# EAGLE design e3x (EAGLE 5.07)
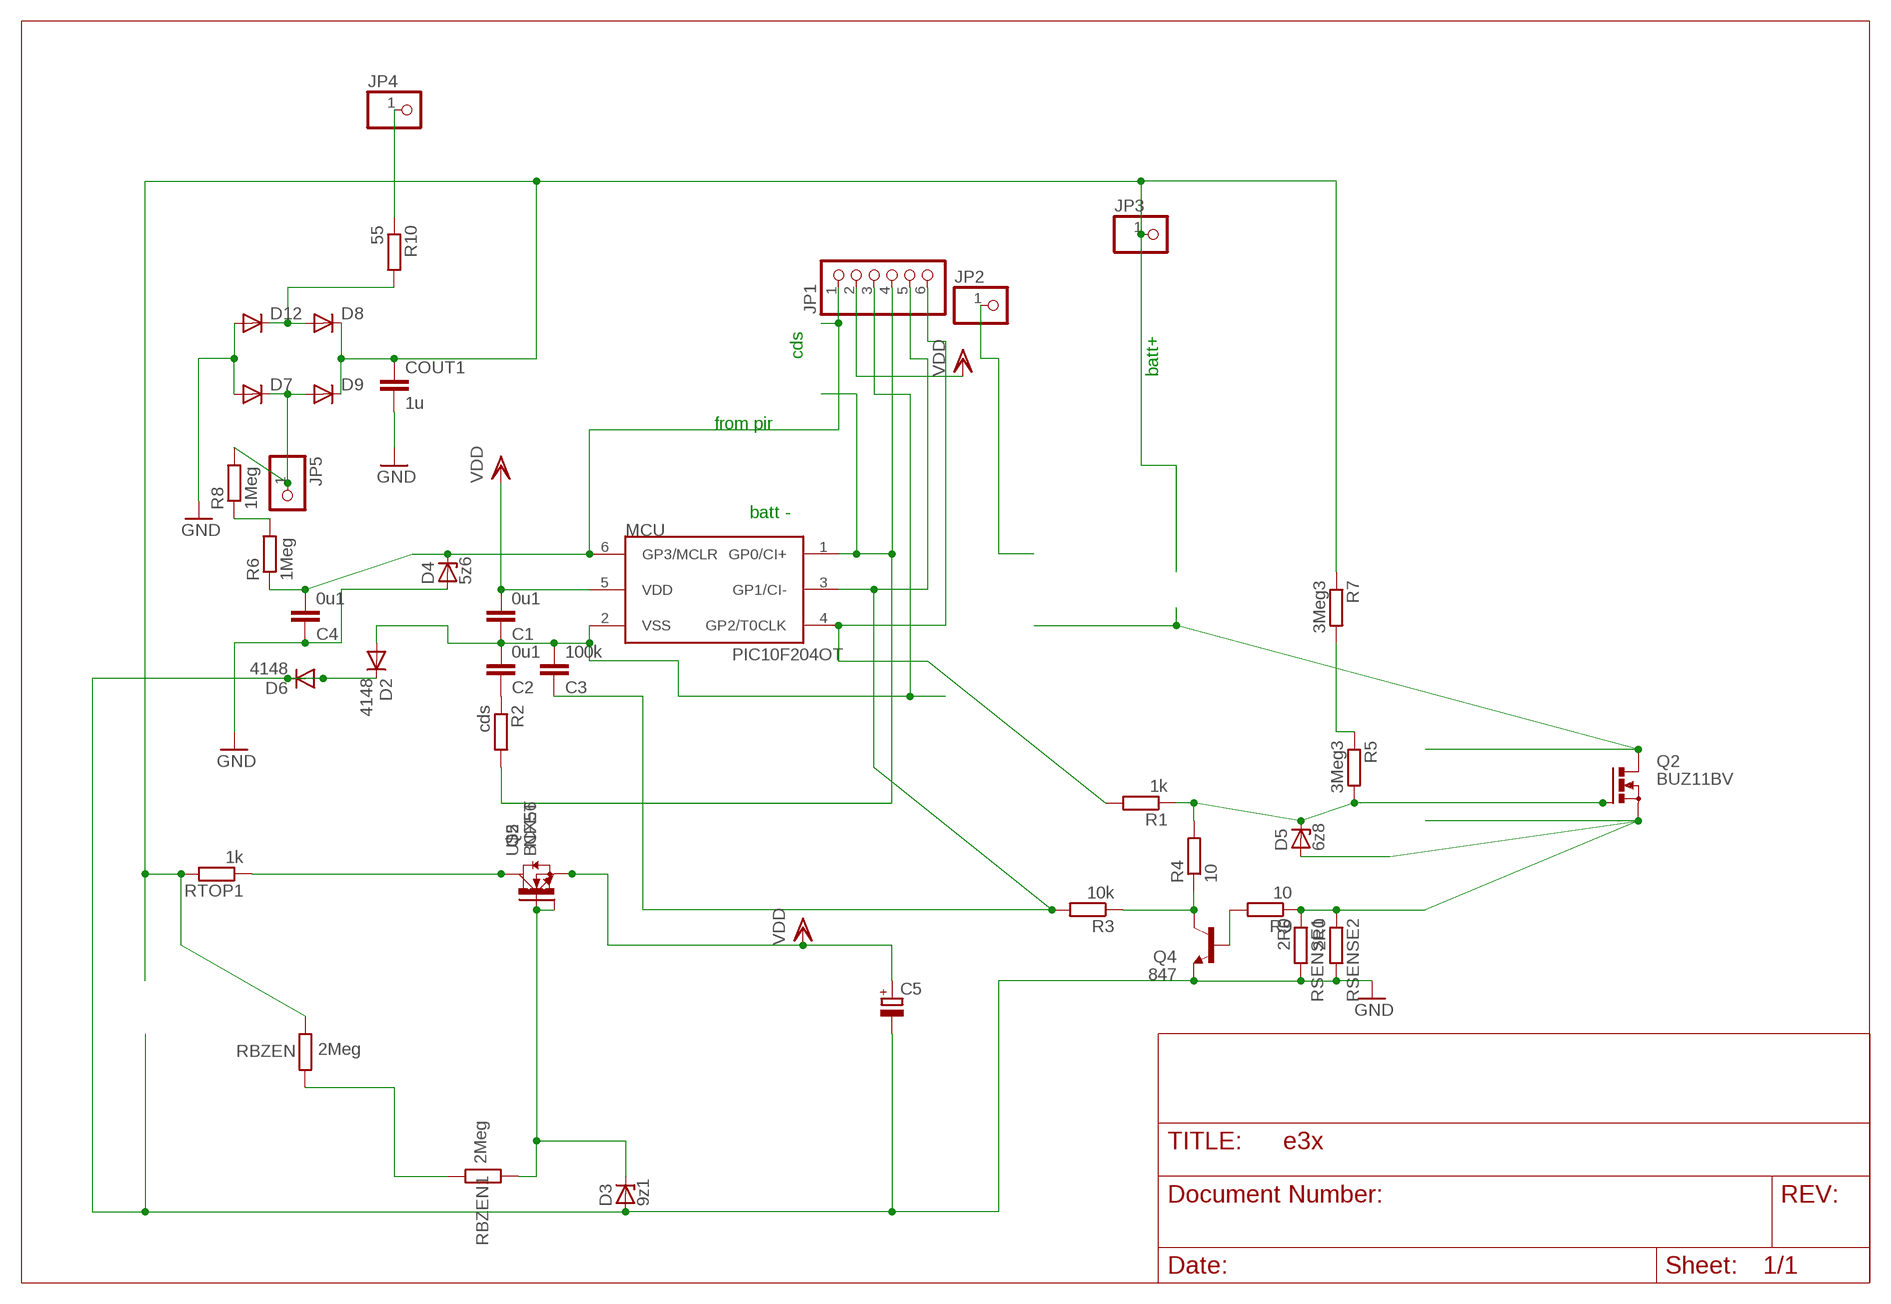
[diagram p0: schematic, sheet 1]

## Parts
C1  0u1  C-EUC0805  [C0805]
C2  0u1  C-EUC0805  [C0805]
C3  100k  C-EUC0805  [C0805]
C4  0u1  C-EUC1206  [C1206]
C5  CPOL-EUSANYO_SMD_C6  [SANYO-OSCON_SMD_C6]
COUT1  1u  C-EU075-032X103  [C075-032X103]
D2  4148  1N4148MINIMELF  [MINIMELF]
D3  9z1  ZENER-DIODESOD80C  [SOD80C]
D4  5z6  ZENER-DIODESOD80C  [SOD80C]
D5  6z8  ZENER-DIODESOD80C  [SOD80C]
D6  4148  1N4148MINIMELF  [MINIMELF]
D7  DIODE-SMA-DO214  [SMA-DO214AC]
D8  DIODE-SMA-DO214  [SMA-DO214AC]
D9  DIODE-SMA-DO214  [SMA-DO214AC]
D12  DIODE-SMA-DO214  [SMA-DO214AC]
JP1  PINHD-1X6  [1X06BOX]
JP2  PINHD-1X11MM6  [1X1MM8]
JP3  PINHD-1X11MM6  [1X1MM8]
JP4  PINHD-1X11MM6  [1X1MM8]
JP5  PINHD-1X11MM6  [1X1MM8]
MCU  PIC10F204OT  [SOT23-6]
Q2  BUZ11BV  [TO220BV]
Q4  847  BC847ASMD  [SOT23]
Q5  NFET  N-HEXFET_DPAK-  [TO252]
R1  1k  R-EU_R0805  [R0805]
R2  cds  R-EU_0204/2V  [0204V]
R3  10k  R-EU_R0805  [R0805]
R4  10  R-EU_R1206  [R1206]
R5  3Meg3  R-EU_R1206  [R1206]
R6  1Meg  R-EU_R1206  [R1206]
R7  3Meg3  R-EU_R1206  [R1206]
R8  1Meg  R-EU_R1206  [R1206]
R9  10  R-EU_R0805  [R0805]
R10  55  R-EU_0207/35  [0207/35]
RBZEN  2Meg  R-EU_R1206  [R1206]
RBZEN1  2Meg  R-EU_R1206  [R1206]
RSENSE1  2R0  R-EU_R1210  [R1210]
RSENSE2  2R0  R-EU_R2512  [R2512]
RTOP1  1k  R-EU_R1206  [R1206]
U$2  BCX56  [SOT223]

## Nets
AC1: JP4.1 R10.1
AC2: D7.K(C) D9.A JP5.1 R8.2
ACR: D8.A D12.K(C) R10.2
C: Q5.3(D) RTOP1.1 U$2.2(C)
CB: D3.C Q5.1(G) RBZEN1.2 U$2.1(B)
GND: C4.1 C5.- COUT1.2 D2.C D3.A D4.A D6.A D6.C D7.A D12.A Q4.2(E) RSENSE1.2 RSENSE2.2
HOT: Q2.D
LED-: JP2.1
N$1: Q4.3(C) R3.1 R4.1
N$2: JP1.4 MCU.1(GP0/CI+) R2.2
N$3: C4.2 D4.C JP1.1 MCU.6(GP3/MCLR) R6.1
N$4: R5.1 R7.2
N$5: C3.1 JP1.5 MCU.3(GP1/CI-) R3.2
N$6: RBZEN1.1 RBZEN.2
N$7: D5.C Q2.G R1.1 R4.2 R5.2
N$8: C2.1 R2.1
N$9: R6.2 R8.1
N$10: Q4.1(B) R9.2
N$14: JP1.6 MCU.4(GP2/T0CLK) R1.2
N$17: D5.A Q2.S R9.1 RSENSE1.1 RSENSE2.1
VDD: C1.2 C5.+ JP1.2 MCU.5(VDD) Q5.2(S) U$2.3(E)
VPLUS: COUT1.1 D8.K(C) D9.K(C) JP3.1 R7.1 RBZEN.1 RTOP1.2
VSS: C1.1 C2.2 C3.2 D2.A JP1.3 MCU.2(VSS)

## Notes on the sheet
- cds
- batt+
- from pir
- batt -

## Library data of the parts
C1-C4 COUT1 = rcl:C-EU: CAPACITOR, European symbol
C5 = rcl-2:CPOL-EU: POLARIZED CAPACITOR, European symbol
D2 D6 = diode-1:1N4148: DIODE
D3-D5 = diode:ZENER-DIODE: Z-Diode
D7-D9 D12 = diode:DIODE-: DIODE
JP1 = pinhead:PINHD-1X6: PIN HEADER
JP2-JP5 = pinhead:PINHD-1X1: PIN HEADER
MCU = microchip-3:PIC10F2*: uPC nW 0,25/0,5k Program Flash memory Comparator
Q2 = transistor-power:BUZ11: N-CHANNEL MOS FET
Q4 = transistor-npn:BC847*: NPN Transistor
Q5 = transistor-power:N-HEXFET_?-*: HEXFET® Power MOSFET
R1-R5 R7 R9 RBZEN RBZEN1 RSENSE1 RSENSE2 RTOP1 = rcl:R-EU_: RESISTOR, European symbol
R6 R8 R10 = rcl-2:R-EU_: RESISTOR, European symbol
U$2 = transistor-power:BCX56

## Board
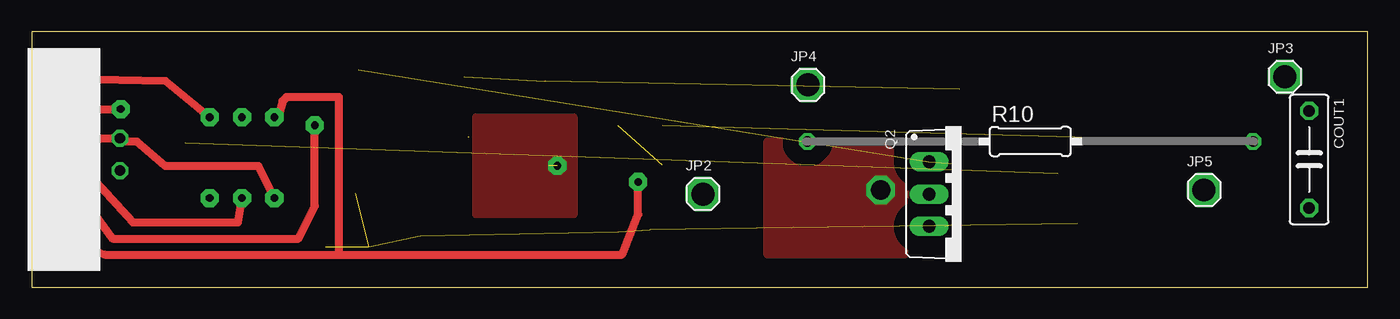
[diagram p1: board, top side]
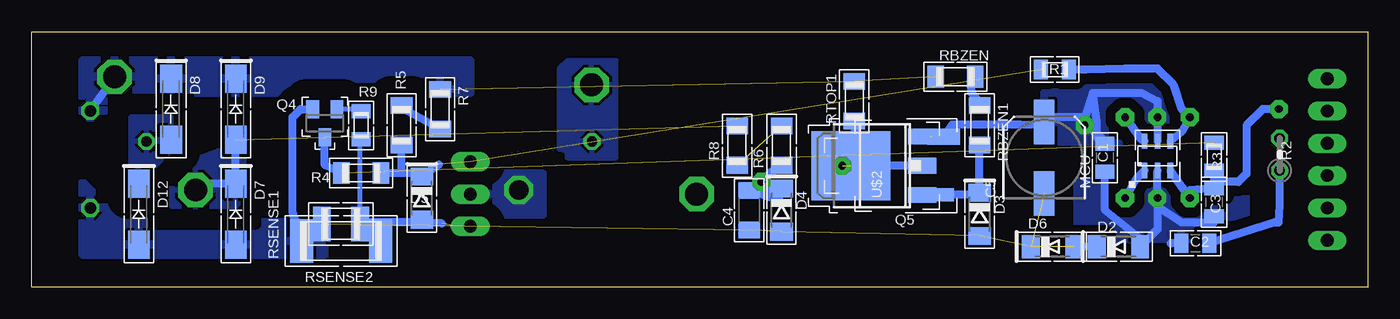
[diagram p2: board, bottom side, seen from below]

Size 104.93 x 20.04 mm. Coordinates in mm from the lower left corner, seen from the top.
Outline: 0,0 104.93,0 104.93,20.04 0,20.04 0,0
Copper layers (1*16): Top 0.035mm / dielectric 1.5mm / Bottom 0.035mm
Design rules "default *": minimum track width 10mil, minimum drill 24mil, track to track 8mil, track to pad 8mil, pad to pad 8mil, via to via 8mil, smd to smd 8mil, copper to edge 20mil, drill to drill 8mil, minimum pad ring 10mil, minimum via ring 8mil, stop-mask expansion 4mil, vias tented up to drill 0mil, thermal gap 10mil

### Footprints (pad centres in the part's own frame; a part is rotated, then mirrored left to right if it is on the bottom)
C0805 = smd 1.1 x 1.5: 1 -1.1,0; 2 1.1,0
C1206 = smd 1.3 x 1.7: 1 -1.55,0; 2 1.55,0
SANYO-OSCON_SMD_C6 = smd 3.5 x 1.6: + 2.8,0; - -2.8,0
C075-032X103 = drill 0.914 octagon: 1 -3.81,0; 2 3.81,0
MINIMELF = smd 1.4 x 1.8: A 1.7,0; C -1.7,0
SOD80C = smd 1.4 x 1.8: A 1.7,0; C -1.7,0
SMA-DO214AC = smd 2.2 x 1.7: A 2.4,0; K -2.4,0
1X06BOX = drill 1 long: 1 -6.35,0; 2 -3.81,0; 3 -1.27,0; 4 1.27,0; 5 3.81,0 | drill 1.016 long: 6 6.35,0
1X1MM8 = drill 1.8 pad 2.54 octagon: 1 0,0
SOT23-6 = smd 0.45 x 1.2: 1 -1.016,-1.15; 2 0,-1.15; 3 1.016,-1.15; 4 1.016,1.15; 5 0,1.15; 6 -1.016,1.15
TO220BV = drill 1.016 long: D 0,-2.54; G -2.54,-2.54; S 2.54,-2.54
SOT23 = smd 1 x 1.4: 1 -0.95,-1.1; 2 0.95,-1.1; 3 0,1.1
TO252 = smd 1 x 1.6: 1 -2.28,-3.53 | smd 1.27 x 2.54: 2 2.28,-3.53 | smd 5.4 x 6.2: 3 0,3.77
R0805 = smd 1.1 x 1.5: 1 -1.1,0; 2 1.1,0
0204V = drill 0.813 octagon: 1 -1.27,0; 2 1.27,0
R1206 = smd 1.3 x 1.7: 1 -1.55,0; 2 1.55,0
0207/35 = drill 0.813 octagon: 1 -17.5,0; 2 17.5,0
R1210 = smd 1.4 x 2.7: 1 -1.5,0; 2 1.5,0
R2512 = smd 1.8 x 3.4: 1 -3.1,0; 2 3.1,0
SOT223 = smd 1.219 x 2.235: 1 -2.311,-3.099; 2 0,-3.099; 3 2.311,-3.099 | smd 3.6 x 2.2: 4 0,3.099

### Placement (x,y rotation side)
C1  20.64,10.16 90 bottom
C2  13.53,3.43 180 bottom
C3  12.06,6.67 270 bottom
C4  48.58,6.03 90 bottom
C5  25.4,10.16 90 bottom
COUT1  100.33,10.02 270 top
D2  19.57,3.17 0 bottom
D3  30.48,5.71 270 bottom
D4  46.04,6.03 270 bottom
D5  74.3,6.98 270 bottom
D6  24.77,3.17 0 bottom
D7  88.9,5.71 270 bottom
D8  93.98,13.97 270 bottom
D9  88.9,13.97 270 bottom
D12  96.52,5.71 270 bottom
JP1  3.17,10.02 90 top
JP2  52.7,7.3 0 top
JP3  98.42,16.51 0 top
JP4  60.96,15.88 0 top
JP5  92.08,7.62 0 top
MCU  16.51,10.3 0 bottom
Q2  73.03,7.3 270 top
Q4  81.92,12.87 180 bottom
Q5  36.83,9.53 90 bottom
R1  24.57,17.08 0 bottom
R2  6.92,10.41 90 bottom
R3  12.06,10.22 270 bottom
R4  79.06,8.95 0 bottom
R5  75.88,12.7 270 bottom
R6  46.04,11.11 90 bottom
R7  72.86,13.97 270 bottom
R8  49.53,11.11 90 bottom
R9  79.06,12.7 90 bottom
R10  78.42,11.43 0 top
RBZEN  32.38,16.51 0 bottom
RBZEN1  30.48,12.7 270 bottom
RSENSE1  80.64,4.95 180 bottom
RSENSE2  80.64,3.62 180 bottom
RTOP1  40.32,14.61 90 bottom
U$2  38.1,9.53 90 bottom

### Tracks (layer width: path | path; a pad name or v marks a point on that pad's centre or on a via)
AC1
  pour Bottom (isolate 1.422, rank 2): 59.05,17.78 62.87,17.78 63.5,17.14 63.5,10.79 62.87,10.16 59.05,10.16
AC2  (1 unrouted)
  Bottom 0.61: D9.A D7.K 92.08,8.12 JP5.1
  pour Bottom (isolate 1.422, rank 2): 88.27,11.43 93.34,9.53 93.98,8.89 93.98,6.35 88.9,6.35 88.27,6.98
ACR
  Bottom 0.61: D8.A 93.98,11.43
  pour Bottom (isolate 1.422): 93.98,13.33 97.16,13.33 97.16,12.06 97.16,8.89 95.89,8.89 93.98,10.79 93.98,12.06
C  (via drill 0.6 pad 1.42)  (1 unrouted)
  Bottom 0.61: 40.01,9.53 40.51,10.54 | 40.51,10.54 40.64,10.79 40.64,11.43 41.27,11.43 | U$2.2 39.37,9.53 | 39.37,9.53 40.01,9.53 | 39.37,9.53 41.91,10.79 | 40.01,9.53 Q5.3 | RTOP1.1 40.17,10.88 40.51,10.54
  other vias: 41.27,9.53
  pour Top (isolate 0.61, rank 4): 34.92,13.33 42.55,13.33 42.55,5.71 34.92,5.71
CB
  Bottom 0.61: RBZEN1.2 D3.C 30.65,7.24 Q5.1 33.33,7.21 U$2.1
GND  (6 unrouted)
  Bottom 0.61: D2.C D6.A | RSENSE1.2 83.48,4.84 RSENSE2.2 84.45,5.89 84.45,13.33 83.82,13.97 Q4.2
  pour Bottom (isolate 1.676, rank 4): 81.92,2.54 81.92,3.17 83.82,5.08 97.79,5.08 100.97,8.26 100.97,2.54
HOT  (via drill 1.5 pad 1.42)
  other vias: 66.67,7.62
  pour Bottom (isolate 1.27): 64.77,8.89 71.12,8.89 71.12,5.71 64.77,5.71
  pour Top (isolate 1.27): 57.78,11.43 66.67,11.43 68.58,9.53 68.58,2.54 57.78,2.54
N$1  (1 unrouted)
  Bottom 0.61: Q4.3 81.92,9.57 R4.1
N$2  (via drill 0.6 pad 1.42)
  Top 0.61: v19.05,6.98 17.78,9.53 10.48,9.53 8.26,11.43 7.18,11.43 R2.2 5.33,11.68 5.08,11.43 3.31,11.43 JP1.4
  Bottom 0.61: MCU.1 18.16,8.51 v19.05,6.98
N$3  (via drill 0.6 pad 1.42)
  Top 0.61: JP1.1 5.71,2.54 24.13,2.54 | 24.13,2.54 24.13,14.92 20,14.92 19.68,14.61 19.37,13.33 v19.05,13.33 | v47.62,8.26 47.62,5.71 46.35,2.54 24.13,2.54
  Bottom 0.61: v19.05,13.33 17.78,11.57 MCU.6 | C4.2 46.34,6.8 D4.C 46.47,7.1 v47.62,8.26 46.83,9.05 R6.1
N$4
  Bottom 0.61: R7.2 75.41,13.82 75.56,13.97 76.05,13.97 R5.1
N$5  (via drill 0.6 pad 1.42)
  Top 0.61: JP1.5 4.45,13.97 v6.99,13.97
  Bottom 0.61: 12.06,8.26 C3.1 13.97,7.62 v13.97,6.98 MCU.3 | 12.06,8.26 R3.2 | v6.99,13.97 8.26,13.97 9.53,12.7 9.53,8.89 10.16,8.26 12.06,8.26
N$6
  Bottom 0.61: RBZEN1.1 30.48,14.61 31.11,15.24 31.11,16.36 RBZEN.2
N$7  (2 unrouted)
  Bottom 0.61: 72.94,9.64 D5.C 74.3,8.95 75.88,8.95 | 75.88,8.95 R4.2 | 75.88,8.95 R5.2
N$8
  Bottom 0.61: R2.1 6.92,6.41 6.99,5.08 7.24,5.08 C2.1
N$9  (1 unrouted)
N$10
  Bottom 0.406: Q4.1 79.06,13.97 R9.2
N$14  (via drill 0.6 pad 1.42)
  Top 0.61: JP1.6 10.48,16.19 v13.97,13.33
  Bottom 0.61: MCU.4 14.61,12.21 v13.97,13.33 14.61,13.97 15.24,15.88 16.51,17.14 19.05,17.14 22.16,17.08 R1.2
N$17  (1 unrouted)
  Bottom 0.406: R9.1 79.14,11.6 RSENSE1.1
  Bottom 0.61: Q2.S 71.73,4.76 | 72.71,5.01 74.3,5.08 74.61,5.08 | 74.61,5.08 76.89,5.08 | 76.89,5.08 RSENSE2.1 | 74.61,5.08 D5.A | 76.89,5.08 78.29,5.08 RSENSE1.1
VDD  (via drill 0.6 pad 1.42)  (1 unrouted)
  Top 0.61: JP1.2 4.58,6.21 6.35,3.81 20.95,3.81 22.23,6.35 v22.23,12.7
  Bottom 0.61: U$2.3 34.34,11.81 | 34.28,11.8 Q5.2 32.65,12.76 27.3,12.76 26.04,12.7 C5.+ 25.4,13.33 22.23,13.33 21.59,15.24 | MCU.5 v16.51,13.33 16.51,14.61 17.78,15.24 21.59,15.24 | 21.59,15.24 21.27,13.02 21.27,11.75 20.95,11.43 C1.2 20.96,11.75 v22.23,12.7
  pour Bottom (isolate 0.813, rank 2): 24.77,11.43 13.34,11.43 13.34,15.24 13.97,15.88 24.77,15.88 26.04,14.61
VPLUS  (2 unrouted)
  Bottom 0.61: COUT1.1 JP3.1
  pour Bottom (isolate 1.676, rank 3): 100.97,13.33 99.06,13.33 93.66,15.24 81.92,15.24 81.28,15.88 74.3,15.88 73.66,15.24 70.48,15.24 70.48,17.78 100.97,17.78
VSS  (via drill 0.6 pad 1.42)
  Top 0.61: JP1.3 4.58,8.75 7.94,5.08 16.19,5.08 v16.51,6.98
  Bottom 0.61: C1.1 20.64,6.03 17.51,3.54 | 17.51,3.54 16.51,4.54 16.51,6.35 | 17.51,3.54 D2.A | 16.51,6.35 v16.51,6.98 MCU.2 | C2.2 15.49,3.43 | 16.51,6.35 14.61,5.08 13.34,5.08 12.06,5.08 C3.2
  pour Bottom (isolate 0.813): 9.53,8.26 22.86,8.26 22.86,3.81 9.53,3.81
